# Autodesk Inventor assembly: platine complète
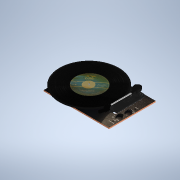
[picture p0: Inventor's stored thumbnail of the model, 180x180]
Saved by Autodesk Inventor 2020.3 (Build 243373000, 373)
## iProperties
Created: 2020-09
Part Number: platine complète
Document SubType Name: Assembly
Designer: ficho
Author: ficho
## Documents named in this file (9)
- G:\travail\année 2020-2021\2I2D\platine disque\platine 3D\platine complète.iam
- G:\travail\année 2020-2021\2I2D\platine disque\platine 3D\CE bras.iam
- G:\travail\année 2020-2021\2I2D\platine disque\platine 3D\CE pivot + butées.iam
- G:\travail\année 2020-2021\2I2D\platine disque\platine 3D\CE platine.iam
- G:\travail\année 2020-2021\2I2D\platine disque\platine 3D\porte platine.ipt
- G:\travail\année 2020-2021\2I2D\platine disque\platine 3D\CE boitier.iam
- G:\travail\année 2020-2021\2I2D\platine disque\platine 3D\moteur cc.ipt
- G:\travail\année 2020-2021\2I2D\platine disque\platine 3D\poulie moteur.ipt
- G:\travail\année 2020-2021\2I2D\platine disque\platine 3D\platine complète\Design Accelerator\Transmission par courroies synchrones1.iam
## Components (8 placed, 8 different names)
1. CE bras:1 [sub-assembly] — Placage:1, Affleurement:1
2. CE pivot + butées:1 [sub-assembly] — Placage:1, Affleurement:1, Logement:1
3. CE platine:1 [sub-assembly] — Logement:2
4. porte platine:1 — Logement:1, Logement:2, Placage:2, Affleurement:2, Placage:3, Logement:3
5. CE boitier:1 [sub-assembly] — Placage:2, Affleurement:2, Placage:3
6. moteur cc:1 — Logement:3, Logement:4
7. poulie moteur:1 — Logement:4
8. Transmission par courroies synchrones:1 [sub-assembly]
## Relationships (9: Insert 4, Mate 3, Flush 2)
- Placage:1 [Mate]: CE bras:1 ↔ CE pivot + butées:1
- Affleurement:1 [Flush]: CE bras:1 ↔ CE pivot + butées:1
- Logement:1 [Insert]: CE pivot + butées:1 ↔ porte platine:1
- Logement:2 [Insert]: CE platine:1 ↔ porte platine:1
- Placage:2 [Mate]: porte platine:1 ↔ CE boitier:1
- Affleurement:2 [Flush]: porte platine:1 ↔ CE boitier:1
- Placage:3 [Mate]: porte platine:1 ↔ CE boitier:1
- Logement:3 [Insert]: porte platine:1 ↔ moteur cc:1
- Logement:4 [Insert]: moteur cc:1 ↔ poulie moteur:1
## Named parameters: sa_1 = 0, sa_2 = 0
